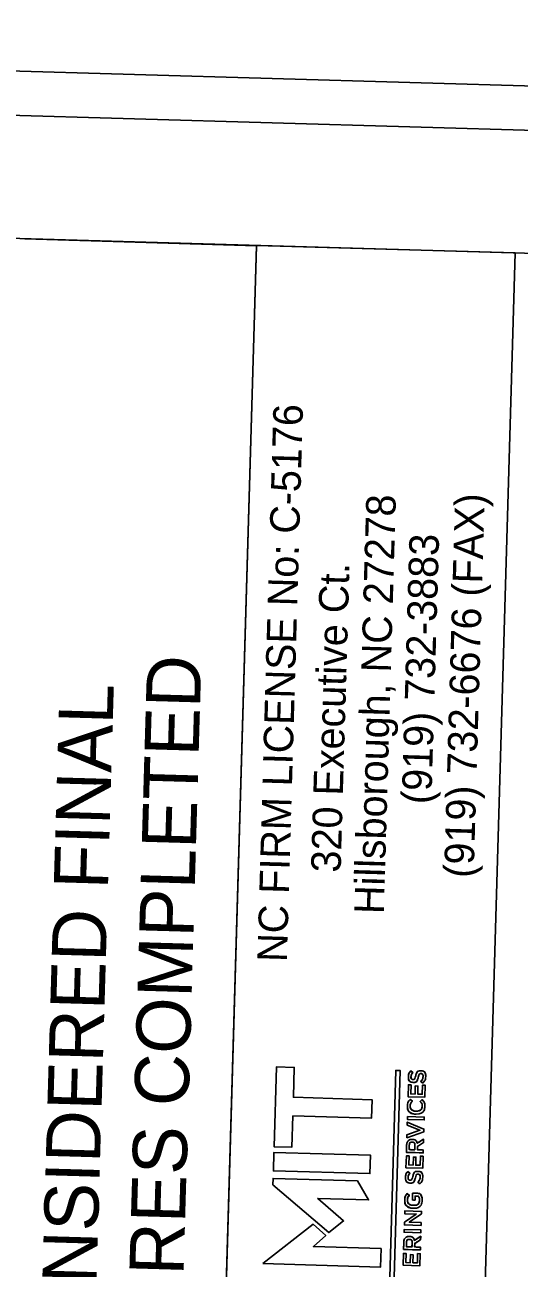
# Model space of a CAD drawing. Extents: x 2097000 to 2098148, y 684979 to 687012.
# Drawn here: x 2097210.5 to 2097260.6, y 686715.9 to 686842.1 of the extents above; entities that cross this region are included whole.
import ezdxf

# ---------------------------------------------------------------- set-up
doc = ezdxf.new("R2010")
doc.units = 0
for name, color, linetype in [('Sheet Block Title CELL', 7, 'Continuous'), ('Sheet Plot Border Inside CELL', 7, 'Continuous'), ('Sheet Plot Border Outside CELL', 7, 'Continuous'), ('Sheet Profile CELL', 7, 'Continuous'), ('Sheet Sticker Exception Certification CELL', 7, 'Continuous')]:
    doc.layers.add(name, color=color, linetype=linetype)

msp = doc.modelspace()

# ---------------------------------------------------------------- linework, layer by layer
at = {"layer": 'Sheet Block Title CELL'}
for p, q in [((2097249.81, 686735.72), (2097249.59, 686735.89)), ((2097250.62, 686735.9), (2097250.61, 686735.9)), ((2097250.63, 686735.62), (2097250.64, 686735.62)), ((2097249.82, 686735.02), (2097249.82, 686735.02)), ((2097249.83, 686734.73), (2097249.84, 686734.73)), ((2097250.61, 686734.81), (2097250.82, 686734.64)), ((2097249.77, 686732.81), (2097249.55, 686733)), ((2097250.74, 686732.98), (2097250.54, 686732.8)), ((2097250.13, 686731.81), (2097250.13, 686731.81)), ((2097250.12, 686731.51), (2097250.13, 686731.51)), ((2097249.74, 686728.94), (2097249.73, 686728.94)), ((2097249.74, 686728.65), (2097249.75, 686728.65)), ((2097249.51, 686725.51), (2097249.29, 686725.67)), ((2097250.32, 686725.69), (2097250.32, 686725.69)), ((2097250.34, 686725.4), (2097250.34, 686725.4)), ((2097249.52, 686724.8), (2097249.52, 686724.8)), ((2097249.54, 686724.51), (2097249.54, 686724.51)), ((2097250.31, 686724.6), (2097250.52, 686724.42)), ((2097249.46, 686723.25), (2097249.24, 686723.44)), ((2097249.84, 686721.95), (2097249.85, 686721.95)), ((2097249.85, 686722.25), (2097249.85, 686722.25)), ((2097249.45, 686719.08), (2097249.45, 686719.08)), ((2097249.46, 686718.79), (2097249.46, 686718.79))]:
    msp.add_line(p, q, dxfattribs=at)
msp.add_lwpolyline([(2097228.13, 686619.71), (2097233.94, 686819.68), (2097260.19, 686818.92), (2097254.37, 686618.95)], close=True, dxfattribs=at)
for points in [[(2097235.97, 686736.29), (2097237.78, 686736.24), (2097237.69, 686733.21), (2097245.68, 686732.97), (2097245.62, 686731.1), (2097237.64, 686731.33), (2097237.54, 686728.15), (2097235.74, 686728.2), (2097235.97, 686736.29)], [(2097235.74, 686728.2), (2097237.54, 686728.15), (2097237.64, 686731.33), (2097245.62, 686731.1), (2097245.68, 686732.97), (2097237.69, 686733.21), (2097237.78, 686736.24), (2097235.97, 686736.29), (2097235.74, 686728.2)], [(2097248.53, 686735.93), (2097247.21, 686690.41), (2097246.76, 686690.42), (2097248.08, 686735.94), (2097248.53, 686735.93)], [(2097248.08, 686735.94), (2097246.76, 686690.42), (2097247.21, 686690.41), (2097248.53, 686735.93), (2097248.08, 686735.94)], [(2097249.32, 686733.27), (2097249.36, 686734.48), (2097249.63, 686734.47), (2097249.6, 686733.55), (2097250.04, 686733.54), (2097250.06, 686734.36), (2097250.33, 686734.35), (2097250.31, 686733.53), (2097250.76, 686733.52), (2097250.79, 686734.45), (2097251.06, 686734.44), (2097251.02, 686733.22), (2097249.32, 686733.27)], [(2097251.02, 686733.22), (2097251.06, 686734.44), (2097250.79, 686734.45), (2097250.76, 686733.52), (2097250.31, 686733.53), (2097250.33, 686734.35), (2097250.06, 686734.36), (2097250.04, 686733.54), (2097249.6, 686733.55), (2097249.63, 686734.47), (2097249.36, 686734.48), (2097249.32, 686733.27), (2097251.02, 686733.22)], [(2097249.2, 686729.1), (2097249.21, 686729.41), (2097250.53, 686729.87), (2097249.24, 686730.39), (2097249.25, 686730.7), (2097250.94, 686729.98), (2097250.93, 686729.72), (2097249.2, 686729.1)], [(2097250.93, 686729.72), (2097250.94, 686729.98), (2097249.25, 686730.7), (2097249.24, 686730.39), (2097250.53, 686729.87), (2097249.21, 686729.41), (2097249.2, 686729.1), (2097250.93, 686729.72)], [(2097249.26, 686730.97), (2097249.27, 686731.26), (2097250.96, 686731.21), (2097250.96, 686730.92), (2097249.26, 686730.97)], [(2097250.96, 686730.92), (2097250.96, 686731.21), (2097249.27, 686731.26), (2097249.26, 686730.97), (2097250.96, 686730.92)], [(2097249.18, 686728.35), (2097249.16, 686727.62), (2097250.86, 686727.57), (2097250.87, 686727.86), (2097250.27, 686727.88), (2097250.29, 686728.23), (2097250.89, 686728.62), (2097250.9, 686728.96), (2097250.24, 686728.54)], [(2097250.02, 686728.3), (2097250.01, 686727.88), (2097249.44, 686727.9), (2097249.45, 686728.32)], [(2097235.66, 686725.74), (2097235.72, 686727.62), (2097245.51, 686727.34), (2097245.46, 686725.46), (2097235.66, 686725.74)], [(2097245.46, 686725.46), (2097245.51, 686727.34), (2097235.72, 686727.62), (2097235.66, 686725.74), (2097245.46, 686725.46)], [(2097249.11, 686726.06), (2097249.15, 686727.27), (2097249.42, 686727.26), (2097249.39, 686726.34), (2097249.83, 686726.33), (2097249.86, 686727.15), (2097250.12, 686727.14), (2097250.1, 686726.32), (2097250.55, 686726.31), (2097250.58, 686727.24), (2097250.85, 686727.23), (2097250.81, 686726.01), (2097249.11, 686726.06)], [(2097250.81, 686726.01), (2097250.85, 686727.23), (2097250.58, 686727.24), (2097250.55, 686726.31), (2097250.1, 686726.32), (2097250.12, 686727.14), (2097249.86, 686727.15), (2097249.83, 686726.33), (2097249.39, 686726.34), (2097249.42, 686727.26), (2097249.15, 686727.27), (2097249.11, 686726.06), (2097250.81, 686726.01)], [(2097235.62, 686724.31), (2097241.29, 686719.48), (2097242.78, 686720.67), (2097240.16, 686722.95), (2097245.32, 686722.8), (2097244.18, 686724.73), (2097235.64, 686724.97), (2097235.62, 686724.31)], [(2097235.62, 686724.31), (2097241.29, 686719.48), (2097242.78, 686720.67), (2097240.16, 686722.95), (2097245.32, 686722.8), (2097244.18, 686724.73), (2097235.64, 686724.97), (2097235.62, 686724.31)], [(2097250.5, 686723.46), (2097249.79, 686723.48), (2097249.77, 686722.79), (2097250.03, 686722.78), (2097250.04, 686723.19), (2097250.36, 686723.19)], [(2097248.95, 686720.26), (2097248.95, 686720.52), (2097250.15, 686721.36), (2097248.98, 686721.39), (2097248.99, 686721.68), (2097250.69, 686721.63), (2097250.68, 686721.39), (2097249.44, 686720.52), (2097250.65, 686720.49), (2097250.64, 686720.21), (2097248.95, 686720.26)], [(2097250.64, 686720.21), (2097250.65, 686720.49), (2097249.44, 686720.52), (2097250.68, 686721.39), (2097250.69, 686721.63), (2097248.99, 686721.68), (2097248.98, 686721.39), (2097250.15, 686721.36), (2097248.95, 686720.52), (2097248.95, 686720.26), (2097250.64, 686720.21)], [(2097234.61, 686716.33), (2097246.54, 686715.98), (2097246.59, 686717.86), (2097239.72, 686718.06), (2097240.98, 686719.19), (2097239.71, 686720.32), (2097234.61, 686716.33)], [(2097234.61, 686716.33), (2097246.54, 686715.98), (2097246.59, 686717.86), (2097239.72, 686718.06), (2097240.98, 686719.19), (2097239.71, 686720.32), (2097234.61, 686716.33)], [(2097248.89, 686718.49), (2097248.87, 686717.77), (2097250.57, 686717.72), (2097250.58, 686718), (2097249.99, 686718.02), (2097250, 686718.38), (2097250.6, 686718.76), (2097250.61, 686719.1), (2097249.96, 686718.68)], [(2097248.92, 686719.51), (2097248.93, 686719.8), (2097250.63, 686719.75), (2097250.62, 686719.46), (2097248.92, 686719.51)], [(2097250.62, 686719.46), (2097250.63, 686719.75), (2097248.93, 686719.8), (2097248.92, 686719.51), (2097250.62, 686719.46)], [(2097249.74, 686718.45), (2097249.72, 686718.03), (2097249.15, 686718.04), (2097249.17, 686718.46)], [(2097248.83, 686716.16), (2097248.86, 686717.37), (2097249.13, 686717.36), (2097249.1, 686716.44), (2097249.54, 686716.42), (2097249.57, 686717.24), (2097249.83, 686717.23), (2097249.81, 686716.42), (2097250.27, 686716.4), (2097250.29, 686717.34), (2097250.56, 686717.33), (2097250.53, 686716.11), (2097248.83, 686716.16)], [(2097250.53, 686716.11), (2097250.56, 686717.33), (2097250.29, 686717.34), (2097250.27, 686716.4), (2097249.81, 686716.42), (2097249.83, 686717.23), (2097249.57, 686717.24), (2097249.54, 686716.42), (2097249.1, 686716.44), (2097249.13, 686717.36), (2097248.86, 686717.37), (2097248.83, 686716.16), (2097250.53, 686716.11)]]:
    msp.add_lwpolyline(points, dxfattribs=at)
for points, degree in [([(2097250.82, 686734.64), (2097250.82, 686734.64), (2097250.61, 686734.81), (2097250.61, 686734.81), (2097250.75, 686734.97), (2097250.84, 686735.12), (2097250.84, 686735.32), (2097250.85, 686735.5), (2097250.76, 686735.61), (2097250.64, 686735.62), (2097250.64, 686735.62), (2097250.63, 686735.62), (2097250.63, 686735.62), (2097250.51, 686735.62), (2097250.44, 686735.56), (2097250.36, 686735.26), (2097250.27, 686734.91), (2097250.15, 686734.72), (2097249.84, 686734.73), (2097249.84, 686734.73), (2097249.83, 686734.73), (2097249.83, 686734.73), (2097249.54, 686734.74), (2097249.35, 686734.98), (2097249.36, 686735.3), (2097249.37, 686735.54), (2097249.45, 686735.72), (2097249.59, 686735.89), (2097249.59, 686735.89), (2097249.81, 686735.72), (2097249.81, 686735.72), (2097249.69, 686735.58), (2097249.63, 686735.44), (2097249.62, 686735.29), (2097249.62, 686735.12), (2097249.7, 686735.02), (2097249.82, 686735.02), (2097249.82, 686735.02), (2097249.82, 686735.02), (2097249.82, 686735.02), (2097249.95, 686735.01), (2097250.01, 686735.09), (2097250.1, 686735.4), (2097250.2, 686735.74), (2097250.33, 686735.91), (2097250.61, 686735.9), (2097250.61, 686735.9), (2097250.62, 686735.9), (2097250.62, 686735.9), (2097250.94, 686735.89), (2097251.12, 686735.65), (2097251.11, 686735.31), (2097251.1, 686735.06), (2097251, 686734.83), (2097250.82, 686734.64)], 3), ([(2097249.59, 686735.89), (2097249.45, 686735.72), (2097249.37, 686735.54), (2097249.36, 686735.3), (2097249.35, 686734.98), (2097249.54, 686734.74), (2097249.83, 686734.73)], 3), ([(2097249.82, 686735.02), (2097249.7, 686735.02), (2097249.62, 686735.12), (2097249.62, 686735.29), (2097249.63, 686735.44), (2097249.69, 686735.58), (2097249.81, 686735.72)], 3), ([(2097250.61, 686735.9), (2097250.33, 686735.91), (2097250.2, 686735.74), (2097250.1, 686735.4), (2097250.01, 686735.09), (2097249.95, 686735.01), (2097249.82, 686735.02)], 3), ([(2097249.84, 686734.73), (2097250.15, 686734.72), (2097250.27, 686734.91), (2097250.36, 686735.26), (2097250.44, 686735.56), (2097250.51, 686735.62), (2097250.63, 686735.62)], 3), ([(2097250.64, 686735.62), (2097250.76, 686735.61), (2097250.85, 686735.5), (2097250.84, 686735.32), (2097250.84, 686735.12), (2097250.75, 686734.97), (2097250.61, 686734.81)], 3), ([(2097250.82, 686734.64), (2097251, 686734.83), (2097251.1, 686735.06), (2097251.11, 686735.31), (2097251.12, 686735.65), (2097250.94, 686735.89), (2097250.62, 686735.9)], 3), ([(2097250.13, 686731.51), (2097250.13, 686731.51), (2097250.12, 686731.51), (2097250.12, 686731.51), (2097249.64, 686731.52), (2097249.25, 686731.88), (2097249.27, 686732.37), (2097249.28, 686732.67), (2097249.39, 686732.85), (2097249.55, 686733), (2097249.55, 686733), (2097249.77, 686732.81), (2097249.77, 686732.81), (2097249.64, 686732.69), (2097249.55, 686732.55), (2097249.54, 686732.36), (2097249.53, 686732.05), (2097249.79, 686731.82), (2097250.13, 686731.81), (2097250.13, 686731.81), (2097250.13, 686731.81), (2097250.13, 686731.81), (2097250.46, 686731.8), (2097250.74, 686732.01), (2097250.75, 686732.33), (2097250.76, 686732.53), (2097250.68, 686732.66), (2097250.54, 686732.8), (2097250.54, 686732.8), (2097250.74, 686732.98), (2097250.74, 686732.98), (2097250.92, 686732.8), (2097251.03, 686732.61), (2097251.03, 686732.31), (2097251.01, 686731.83), (2097250.62, 686731.49), (2097250.13, 686731.51)], 3), ([(2097249.55, 686733), (2097249.39, 686732.85), (2097249.28, 686732.67), (2097249.27, 686732.37), (2097249.25, 686731.88), (2097249.64, 686731.52), (2097250.12, 686731.51)], 3), ([(2097250.13, 686731.51), (2097250.62, 686731.49), (2097251.01, 686731.83), (2097251.03, 686732.31), (2097251.03, 686732.61), (2097250.92, 686732.8), (2097250.74, 686732.98)], 3), ([(2097250.13, 686731.81), (2097249.79, 686731.82), (2097249.53, 686732.05), (2097249.54, 686732.36), (2097249.55, 686732.55), (2097249.64, 686732.69), (2097249.77, 686732.81)], 3), ([(2097250.54, 686732.8), (2097250.68, 686732.66), (2097250.76, 686732.53), (2097250.75, 686732.33), (2097250.74, 686732.01), (2097250.46, 686731.8), (2097250.13, 686731.81)], 3), ([(2097249.16, 686727.62), (2097249.16, 686727.62), (2097249.18, 686728.35), (2097249.18, 686728.35), (2097249.19, 686728.55), (2097249.25, 686728.71), (2097249.36, 686728.81), (2097249.46, 686728.9), (2097249.59, 686728.94), (2097249.73, 686728.94), (2097249.73, 686728.94), (2097249.74, 686728.94), (2097249.74, 686728.94), (2097250.02, 686728.93), (2097250.18, 686728.76), (2097250.24, 686728.54), (2097250.24, 686728.54), (2097250.9, 686728.96), (2097250.9, 686728.96), (2097250.9, 686728.96), (2097250.89, 686728.62), (2097250.89, 686728.62), (2097250.89, 686728.62), (2097250.29, 686728.23), (2097250.29, 686728.23), (2097250.29, 686728.23), (2097250.27, 686727.88), (2097250.27, 686727.88), (2097250.27, 686727.88), (2097250.87, 686727.86), (2097250.87, 686727.86), (2097250.87, 686727.86), (2097250.86, 686727.57), (2097250.86, 686727.57), (2097250.86, 686727.57), (2097249.16, 686727.62), (2097249.16, 686727.62)], 3), ([(2097249.73, 686728.94), (2097249.59, 686728.94), (2097249.46, 686728.9), (2097249.36, 686728.81), (2097249.25, 686728.71), (2097249.19, 686728.55), (2097249.18, 686728.35)], 3), ([(2097250.02, 686728.3), (2097250.03, 686728.51), (2097249.92, 686728.64), (2097249.75, 686728.65), (2097249.75, 686728.65), (2097249.74, 686728.65), (2097249.74, 686728.65), (2097249.56, 686728.65), (2097249.46, 686728.53), (2097249.45, 686728.32), (2097249.45, 686728.32), (2097249.44, 686727.9), (2097249.44, 686727.9), (2097249.44, 686727.9), (2097250.01, 686727.88), (2097250.01, 686727.88), (2097250.01, 686727.88), (2097250.02, 686728.3), (2097250.02, 686728.3)], 3), ([(2097249.45, 686728.32), (2097249.46, 686728.53), (2097249.56, 686728.65), (2097249.74, 686728.65)], 2), ([(2097250.24, 686728.54), (2097250.18, 686728.76), (2097250.02, 686728.93), (2097249.74, 686728.94)], 2), ([(2097249.75, 686728.65), (2097249.92, 686728.64), (2097250.03, 686728.51), (2097250.02, 686728.3)], 2), ([(2097250.52, 686724.42), (2097250.52, 686724.42), (2097250.31, 686724.6), (2097250.31, 686724.6), (2097250.46, 686724.75), (2097250.54, 686724.91), (2097250.55, 686725.11), (2097250.55, 686725.28), (2097250.47, 686725.4), (2097250.34, 686725.4), (2097250.34, 686725.4), (2097250.34, 686725.4), (2097250.34, 686725.4), (2097250.22, 686725.41), (2097250.15, 686725.34), (2097250.07, 686725.04), (2097249.97, 686724.7), (2097249.86, 686724.5), (2097249.54, 686724.51), (2097249.54, 686724.51), (2097249.54, 686724.51), (2097249.54, 686724.51), (2097249.25, 686724.52), (2097249.05, 686724.76), (2097249.06, 686725.09), (2097249.07, 686725.32), (2097249.15, 686725.51), (2097249.29, 686725.67), (2097249.29, 686725.67), (2097249.51, 686725.51), (2097249.51, 686725.51), (2097249.4, 686725.37), (2097249.33, 686725.22), (2097249.33, 686725.07), (2097249.32, 686724.91), (2097249.41, 686724.8), (2097249.52, 686724.8), (2097249.52, 686724.8), (2097249.52, 686724.8), (2097249.52, 686724.8), (2097249.66, 686724.8), (2097249.72, 686724.87), (2097249.8, 686725.18), (2097249.9, 686725.52), (2097250.03, 686725.7), (2097250.32, 686725.69), (2097250.32, 686725.69), (2097250.32, 686725.69), (2097250.32, 686725.69), (2097250.64, 686725.68), (2097250.82, 686725.43), (2097250.81, 686725.09), (2097250.8, 686724.84), (2097250.71, 686724.61), (2097250.52, 686724.42)], 3), ([(2097249.29, 686725.67), (2097249.15, 686725.51), (2097249.07, 686725.32), (2097249.06, 686725.09), (2097249.05, 686724.76), (2097249.25, 686724.52), (2097249.54, 686724.51)], 3), ([(2097249.52, 686724.8), (2097249.41, 686724.8), (2097249.32, 686724.91), (2097249.33, 686725.07), (2097249.33, 686725.22), (2097249.4, 686725.37), (2097249.51, 686725.51)], 3), ([(2097250.32, 686725.69), (2097250.03, 686725.7), (2097249.9, 686725.52), (2097249.8, 686725.18), (2097249.72, 686724.87), (2097249.66, 686724.8), (2097249.52, 686724.8)], 3), ([(2097249.54, 686724.51), (2097249.86, 686724.5), (2097249.97, 686724.7), (2097250.07, 686725.04), (2097250.15, 686725.34), (2097250.22, 686725.41), (2097250.34, 686725.4)], 3), ([(2097250.34, 686725.4), (2097250.47, 686725.4), (2097250.55, 686725.28), (2097250.55, 686725.11), (2097250.54, 686724.91), (2097250.46, 686724.75), (2097250.31, 686724.6)], 3), ([(2097250.52, 686724.42), (2097250.71, 686724.61), (2097250.8, 686724.84), (2097250.81, 686725.09), (2097250.82, 686725.43), (2097250.64, 686725.68), (2097250.32, 686725.69)], 3), ([(2097249.85, 686721.95), (2097249.85, 686721.95), (2097249.84, 686721.95), (2097249.84, 686721.95), (2097249.37, 686721.97), (2097248.98, 686722.33), (2097248.99, 686722.82), (2097249, 686723.1), (2097249.09, 686723.27), (2097249.24, 686723.44), (2097249.24, 686723.44), (2097249.46, 686723.25), (2097249.46, 686723.25), (2097249.34, 686723.13), (2097249.27, 686723.01), (2097249.26, 686722.8), (2097249.26, 686722.5), (2097249.52, 686722.26), (2097249.85, 686722.25), (2097249.85, 686722.25), (2097249.85, 686722.25), (2097249.85, 686722.25), (2097250.2, 686722.24), (2097250.47, 686722.46), (2097250.48, 686722.79), (2097250.48, 686722.94), (2097250.43, 686723.08), (2097250.36, 686723.19), (2097250.36, 686723.19), (2097250.04, 686723.19), (2097250.04, 686723.19), (2097250.04, 686723.19), (2097250.03, 686722.78), (2097250.03, 686722.78), (2097250.03, 686722.78), (2097249.77, 686722.79), (2097249.77, 686722.79), (2097249.77, 686722.79), (2097249.79, 686723.48), (2097249.79, 686723.48), (2097249.79, 686723.48), (2097250.5, 686723.46), (2097250.5, 686723.46), (2097250.64, 686723.29), (2097250.76, 686723.06), (2097250.75, 686722.77), (2097250.73, 686722.26), (2097250.35, 686721.94), (2097249.85, 686721.95)], 3), ([(2097249.24, 686723.44), (2097249.09, 686723.27), (2097249, 686723.1), (2097248.99, 686722.82), (2097248.98, 686722.33), (2097249.37, 686721.97), (2097249.84, 686721.95)], 3), ([(2097249.85, 686722.25), (2097249.52, 686722.26), (2097249.26, 686722.5), (2097249.26, 686722.8), (2097249.27, 686723.01), (2097249.34, 686723.13), (2097249.46, 686723.25)], 3), ([(2097249.85, 686721.95), (2097250.35, 686721.94), (2097250.73, 686722.26), (2097250.75, 686722.77), (2097250.76, 686723.06), (2097250.64, 686723.29), (2097250.5, 686723.46)], 3), ([(2097250.36, 686723.19), (2097250.43, 686723.08), (2097250.48, 686722.94), (2097250.48, 686722.79), (2097250.47, 686722.46), (2097250.2, 686722.24), (2097249.85, 686722.25)], 3), ([(2097248.87, 686717.77), (2097248.87, 686717.77), (2097248.89, 686718.49), (2097248.89, 686718.49), (2097248.9, 686718.7), (2097248.97, 686718.86), (2097249.08, 686718.96), (2097249.17, 686719.04), (2097249.3, 686719.09), (2097249.45, 686719.08), (2097249.45, 686719.08), (2097249.45, 686719.08), (2097249.45, 686719.08), (2097249.73, 686719.07), (2097249.9, 686718.91), (2097249.96, 686718.68), (2097249.96, 686718.68), (2097250.61, 686719.1), (2097250.61, 686719.1), (2097250.61, 686719.1), (2097250.6, 686718.76), (2097250.6, 686718.76), (2097250.6, 686718.76), (2097250, 686718.38), (2097250, 686718.38), (2097250, 686718.38), (2097249.99, 686718.02), (2097249.99, 686718.02), (2097249.99, 686718.02), (2097250.58, 686718), (2097250.58, 686718), (2097250.58, 686718), (2097250.57, 686717.72), (2097250.57, 686717.72), (2097250.57, 686717.72), (2097248.87, 686717.77), (2097248.87, 686717.77)], 3), ([(2097249.45, 686719.08), (2097249.3, 686719.09), (2097249.17, 686719.04), (2097249.08, 686718.96), (2097248.97, 686718.86), (2097248.9, 686718.7), (2097248.89, 686718.49)], 3), ([(2097249.96, 686718.68), (2097249.9, 686718.91), (2097249.73, 686719.07), (2097249.45, 686719.08)], 2), ([(2097249.74, 686718.45), (2097249.74, 686718.65), (2097249.63, 686718.78), (2097249.46, 686718.79), (2097249.46, 686718.79), (2097249.46, 686718.79), (2097249.46, 686718.79), (2097249.27, 686718.8), (2097249.17, 686718.67), (2097249.17, 686718.46), (2097249.17, 686718.46), (2097249.15, 686718.04), (2097249.15, 686718.04), (2097249.15, 686718.04), (2097249.72, 686718.03), (2097249.72, 686718.03), (2097249.72, 686718.03), (2097249.74, 686718.45), (2097249.74, 686718.45)], 3), ([(2097249.17, 686718.46), (2097249.17, 686718.67), (2097249.27, 686718.8), (2097249.46, 686718.79)], 2), ([(2097249.46, 686718.79), (2097249.63, 686718.78), (2097249.74, 686718.65), (2097249.74, 686718.45)], 2)]:
    msp.add_open_spline(points, degree=degree, dxfattribs=at)
at = {"layer": 'Sheet Plot Border Inside CELL'}
msp.add_lwpolyline([(2098077, 685140.47), (2098125.43, 686806.26), (2097070.77, 686836.92), (2097022.35, 685171.13)], close=True, dxfattribs=at)
at = {"layer": 'Sheet Plot Border Outside CELL'}
msp.add_lwpolyline([(2098099.07, 685126.82), (2098148, 686810.11), (2097048.47, 686842.07), (2096999.53, 685158.79)], close=True, dxfattribs=at)
at = {"layer": 'Sheet Profile CELL'}
msp.add_lwpolyline([(2097072.96, 686824.36), (2097029.37, 685324.99), (2098078.93, 685294.48), (2098122.52, 686793.84)], close=True, dxfattribs=at)
at = {"layer": 'Sheet Sticker Exception Certification CELL'}
for p, q in [((2097210.46, 686820.35), (2097233.95, 686819.66)), ((2097233.94, 686819.66), (2097228.13, 686619.71))]:
    msp.add_line(p, q, dxfattribs=at)

# ---------------------------------------------------------------- texts
at = {"layer": 'Sheet Block Title CELL'}
for s, p in [('NC FIRM LICENSE No: C-5176', (2097237.03, 686746.92)), ('Hillsborough, NC 27278', (2097246.86, 686751.78)), ('(919) 732-6676 (FAX)', (2097255.97, 686755.46)), ('(919) 732-3883', (2097251.68, 686762.94)), ('320 Executive Ct.', (2097242.48, 686756))]:
    msp.add_text(s, height=3.0009, rotation=88.3348, dxfattribs=at).set_placement(p)
at = {"layer": 'Sheet Sticker Exception Certification CELL'}
for s, p in [('UNLESS ALL SIGNATURES COMPLETED', (2097224.24, 686635.83)), ('DOCUMENT NOT CONSIDERED FINAL', (2097215.59, 686641.15))]:
    msp.add_text(s, height=5.5, rotation=88.3348, dxfattribs=at).set_placement(p)

doc.saveas('drawing.dxf')
